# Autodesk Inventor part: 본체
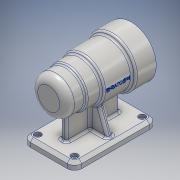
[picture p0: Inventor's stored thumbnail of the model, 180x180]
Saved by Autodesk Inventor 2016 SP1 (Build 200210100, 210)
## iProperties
Created: 2016-06
Part Number: 본체
Material: 알루미늄 6061
Document SubType Name: Modeling
Designer: basic
Density: 2.7 g/cm^3
Appearance: 알루미늄 - 평지
Mass: 671.088 g
Surface Area: 648.112 cm^2
Volume: 248.551 cm^3
Author: basic
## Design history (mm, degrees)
sketch "스케치1"
  geometry: L1 (35, 56)-(-35, 56); L2 (-35, 56)-(-35, -56); L3 (-35, -56)-(35, -56); L4 (35, -56)-(35, 56); L5 (35, 56)-(-35, -56); L6 (-35, 56)-(35, -56); 1 further point
  constraints: 12 end point, 2 midpoint, 2 parallel, 1 horizontal, 1 perpendicular
  dimensions: "d0" = 112 distance of L1.end L2.end; "d1" = 70 distance of L1.start L1.end
extrude "돌출1" new body sketch "스케치1" distance "d2" = 10; taper "d3" = 0 deg
fillet "모깎기1" dims "d4" = 10
sketch "스케치2"
  geometry: L1 (25, 46)-(-25, 46); L2 (-25, 46)-(-25, -46); L3 (-25, -46)-(25, -46); L4 (25, -46)-(25, 46); L5 (25, 46)-(-25, -46); L6 (-25, 46)-(25, -46); 5 further points
  constraints: 12 end point, 4 coincident, 2 midpoint, 2 parallel, 1 horizontal, 1 perpendicular
  dimensions: "d9" = 92 distance of L1.end L2.end; "d10" = 50 distance of L2.end L3.end
hole "구멍1" sketch "스케치2" at (-25, -46), (-25, 46), (25, 46), (25, -46) diameter "d11" = 5; stored, may be unused: countersink angle "d15" = 90 deg, drill point angle "d17" = 118 deg; dims "d12" = 6, "d13" = 9, "d14" = 4, "d16" = 8
chamfer "모따기1" distance "d18" = 4; stored, may be unused: second distance "d19" = 2, angle "d20" = 45 deg
sketch "스케치3"
  geometry: L1 (-56, 70)-(56, 70); L2 (-46, 0)-(46, 0) reference; L3 (-56, 70)-(-56, 95); L4 (-56, 95)-(-31, 95); L5 (-31, 95)-(-31, 97); L6 (-31, 97)-(-11, 97); L7 (-11, 97)-(-11, 100); L8 (-11, 100)-(28, 100); L9 (28, 100)-(28, 104); L10 (28, 104)-(56, 104); L11 (56, 104)-(56, 70); 3 further points
  constraints: 20 end point, 4 perpendicular, 3 parallel, 2 midpoint, 2 vertical, 1 horizontal, 1 vertical alignment
  dimensions: "d21" = 70 distance between parallel lines of L2 L1; "d22" = 112 distance of L1.start L1.end; "d23" = 25 distance of L3.end L4.end; "d24" = 45 distance between parallel lines of L3 L7; "d25" = 84 distance between parallel lines of L3 L9; "d26" = 68 diameter of L10 L1; "d27" = 60 diameter of L8 L1; "d28" = 54 diameter of L6 L1; "d29" = 50 diameter of L4 L1
revolve "회전1" sketch "스케치3" stored, may be unused: angle "d30" = 90 deg
sketch "스케치4"
  geometry: L1 (-56, 45)-(-56, 95) reference; L2 (-56, 70)-(56, 70); L3 (56, 36)-(56, 104) reference; L4 (52, 10)-(56, 6) reference; L5 (56, 6)-(56, 0) reference; L6 (56, 0)-(-56, 0) reference; L7 (-56, 0)-(-56, 6) reference; L8 (-56, 6)-(-52, 10) reference; L9 (-52, 10)-(52, 10) reference; L10 (-56, 45)-(-56, 95) reference; L11 (-56, 95)-(-31, 95) reference; L12 (-31, 95)-(-31, 97) reference; L13 (-31, 97)-(-11, 97) reference; L14 (-11, 97)-(-11, 100) reference; L15 (-11, 100)-(28, 100) reference; L16 (28, 100)-(28, 104) reference; L17 (28, 104)-(56, 104) reference; L18 (56, 104)-(56, 36) reference; L19 (56, 36)-(28, 36) reference; L20 (28, 36)-(28, 40) reference; L21 (28, 40)-(-11, 40) reference; L22 (-11, 40)-(-11, 43) reference; L23 (-11, 43)-(-31, 43) reference; L24 (-31, 43)-(-31, 45) reference; L25 (-31, 45)-(-56, 45) reference; L26 (-50, 70)-(-50, 80.5); L27 (-50, 80.5)-(-47, 80.5); L28 (-47, 80.5)-(-47, 86); L29 (-47, 86)-(-43, 86); L30 (-43, 86)-(-43, 87.5); L31 (-43, 87.5)-(-25, 87.5); L32 (-25, 87.5)-(-25, 91); L33 (-25, 91)-(-13, 91); L34 (-13, 91)-(-13, 94); L35 (-13, 94)-(41, 94); L36 (41, 94)-(41, 91); L37 (41, 91)-(56, 91); L38 (56, 91)-(56, 70); 1 further point
  constraints: 28 end point, 11 perpendicular, 2 midpoint, 2 point on line, 1 collinear, 1 vertical
  dimensions: "d31" = 3 distance of L26.end L27.end; "d32" = 4 distance of L28.end L29.end; "d34" = 21 diameter of L27 L2; "d35" = 32 diameter of L29 L2; "d36" = 35 diameter of L31 L2; "d37" = 42 diameter of L33 L2; "d38" = 48 diameter of L35 L2; "d39" = 42 diameter of L37 L2; "d40" = 15 distance of L36.end L37.end; "d41" = 54 distance of L34.end L35.end; "d42" = 12 distance of L32.end L33.end; "d43" = 18 distance of L30.end L31.end
revolve "회전2" sketch "스케치4" stored, may be unused: angle "d44" = 90 deg
fillet "모깎기2" dims "d45" = 10
sketch "스케치6"
  geometry: L1 (-4, -36)-(4, -36); L2 (4, -36)-(4, 36); L3 (4, 36)-(-4, 36); L4 (-4, 36)-(-4, -36); L5 (4, -36)-(-4, 36); L6 (-25, -56)-(25, -56) reference; 2 further points
  constraints: 10 end point, 2 parallel, 1 coincident, 1 horizontal, 1 midpoint, 1 perpendicular
  dimensions: "d48" = 20 distance between parallel lines of L6 L1; "d49" = 8 distance between parallel lines of L2 L4
extrude "돌출2" join sketch "스케치6" stored distance "d50" = 10; taper "d51" = 0 deg
sketch "스케치7"
  geometry: L1 (-35, 6)-(-31, 10) reference; L2 (-31, 10)-(-4, 10) reference; L3 (-4, 10)-(-4, 40.268) reference; L4 (4, 40.268)-(4, 10) reference; L5 (4, 10)-(31, 10) reference; L6 (31, 10)-(35, 6) reference; L7 (35, 6)-(35, 0) reference; L8 (35, 0)-(-35, 0) reference; L9 (-35, 0)-(-35, 6) reference; L10 (-15.509, 44.32)-(-28, 10); L11 (-25, 10)-(25, 10) reference; C1 r 24 at (0, 70) reference; A1 r 30 centre (0, 70) between (4, 40.268) and (-4, 40.268) reference; 1 further point
  constraints: 2 end point, 1 point on circle, 1 point on line
  dimensions: "d52" = 7 horizontal distance of L8.end L10.end; "d54" = 110 deg angle of L10 L2
feature "리브1" sketch "스케치7" dims "d56" = 1, "d57" = 8, "d58" = 0, "d59" = 0, "d60" = 1, "d61" = 1
sketch "스케치8"
  geometry: L1 (0, 0)-(0, -26); C1 r 25 at (0, 0) reference; 2 further points
  constraints: 2 end point, 1 coincident, 1 vertical
  dimensions: "d62" = 26 distance of L1.start L1.end
hole "구멍2" sketch "스케치8" at (0, -26) diameter "d63" = 3.242; stored, may be unused: countersink angle "d67" = 90 deg, drill point angle "d69" = 118 deg; dims "d64" = 8, "d65" = 9, "d66" = 4, "d68" = 11
fillet "모깎기3" dims "d73" = 3
fillet "모깎기4" dims "d74" = 3
fillet "모깎기6" dims "d76" = 3
fillet "모깎기7" dims "d77" = 3
fillet "모깎기8" dims "d78" = 3
fillet "모깎기10" dims "d82" = 3
chamfer "모따기2" distance "d83" = 1; stored, may be unused: second distance "d84" = 2, angle "d85" = 45 deg
fillet "모깎기12" dims "d87" = 0.3
node "작업 평면2"
sketch "스케치11"
  geometry: L1 (-8.804, 70)-(25, 70) reference; L2 (56, 54)-(30.657, 54) reference; L3 (56, 86)-(56, 54) reference; L4 (30.657, 86)-(56, 86) reference; L5 (54.66, 0)-(-54.66, 0) reference; L6 (-54.66, 0)-(-54.66, 6) reference; L7 (-49.317, 10)-(-2.061, 10) reference; L8 (-1, 10.002)-(1, 10.002) reference; L9 (2.061, 10)-(49.317, 10) reference; L10 (54.66, 6)-(54.66, 0) reference; L11 (56, 36)-(56, 104) reference; 5 further points
  constraints: 1 horizontal alignment, 1 midpoint, 9 other
  dimensions: "d89" = 48 distance from line of L11 point (8, 70)
feature "엠보싱1" sketch "스케치11" dims "d0" = 112, "d1" = 70, "d90" = 0.5, "d91" = 0
node "솔리드1"
mirror "대칭1"
pattern_circular "원형 패턴1" dims angle "d71" = 360 deg
node "절단 모서리 투영1"
node "절단 모서리 투영3"
node "절단 모서리 투영5"
